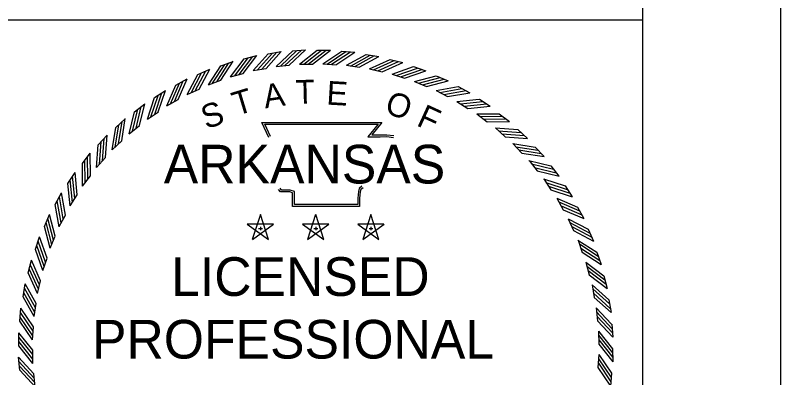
# Model space of a CAD drawing. Extents: x 0 to 1228740, y 0 to 152440.
# Drawn here: x 30.801 to 34, y 18.649 to 20.162 of the extents above; entities that cross this region are included whole.
import ezdxf

# ---------------------------------------------------------------- set-up
doc = ezdxf.new("R2010")
doc.units = 0
doc.layers.add('R_Border', color=7, linetype='Continuous')
doc.layers.add('STAMP_PP', color=7, linetype='Continuous')

msp = doc.modelspace()

# ---------------------------------------------------------------- linework, layer by layer
at = {"layer": 'R_Border'}
for p, q in [((33.4231, 0.5768), (33.4231, 21.4232)), ((29.1131, 20.1432), (33.4231, 20.1432))]:
    msp.add_line(p, q, dxfattribs=at)
msp.add_lwpolyline([(34, 22), (0, 22), (0, 0), (34, 0)], close=True, dxfattribs=at)
at = {"layer": 'STAMP_PP'}
for p, q in [((31.7579, 19.981), (31.8105, 19.9948)), ((31.8584, 20.0015), (31.912, 20.0109)), ((31.9602, 20.0137), (32.0144, 20.0186)), ((32.0633, 20.0167), (32.1177, 20.0167)), ((32.1652, 20.0126), (32.2194, 20.0086)), ((32.2669, 19.9994), (32.3206, 19.9909)), ((31.6595, 19.9522), (31.7108, 19.9703)), ((32.3671, 19.9778), (32.42, 19.965)), ((31.5637, 19.9154), (31.6134, 19.9377)), ((31.7953, 19.9316), (31.849, 19.941)), ((31.8916, 19.9492), (31.9459, 19.9542)), ((31.989, 19.9588), (32.0435, 19.9588)), ((32.0869, 19.9603), (32.1413, 19.9563)), ((32.1845, 19.9538), (32.2384, 19.9453)), ((32.2813, 19.9392), (32.3343, 19.9263)), ((32.4653, 19.9481), (32.5169, 19.9309)), ((31.7008, 19.9061), (31.7536, 19.9199)), ((32.3766, 19.9166), (32.4283, 19.8994)), ((32.5606, 19.9103), (32.6107, 19.8889)), ((31.4714, 19.8708), (31.519, 19.8972)), ((31.6088, 19.8729), (31.6602, 19.891)), ((32.4696, 19.8863), (32.5198, 19.8648)), ((31.383, 19.8188), (31.4283, 19.849)), ((31.5198, 19.8321), (31.5695, 19.8545)), ((32.5598, 19.8484), (32.608, 19.8229)), ((32.6526, 19.8648), (32.7006, 19.8393)), ((31.4344, 19.7842), (31.4821, 19.8106)), ((32.6466, 19.8031), (32.6926, 19.7737)), ((32.7404, 19.8119), (32.7862, 19.7825)), ((31.2992, 19.7596), (31.3419, 19.7934)), ((31.3533, 19.7294), (31.3987, 19.7597)), ((32.7294, 19.7509), (32.7727, 19.7178)), ((32.8235, 19.7518), (32.8668, 19.7188)), ((31.2206, 19.6937), (31.2603, 19.7309)), ((31.277, 19.6681), (31.3198, 19.702)), ((32.8076, 19.692), (32.848, 19.6554)), ((32.9015, 19.6851), (32.9418, 19.6487)), ((31.1477, 19.6216), (31.1842, 19.6619)), ((31.2061, 19.6007), (31.2459, 19.638)), ((32.8806, 19.6268), (32.9179, 19.587)), ((32.9736, 19.6123), (33.0108, 19.5726)), ((31.0811, 19.5437), (31.1141, 19.5869)), ((31.1409, 19.5277), (31.1775, 19.5681)), ((32.948, 19.5558), (32.9819, 19.5131)), ((33.0395, 19.5337), (33.0733, 19.491)), ((31.021, 19.4605), (31.0504, 19.5063)), ((31.082, 19.4495), (31.1151, 19.4928)), ((33.0093, 19.4796), (33.0396, 19.4342)), ((30.9681, 19.3727), (30.9935, 19.4207)), ((33.0987, 19.4499), (33.1288, 19.4046)), ((31.0298, 19.3667), (31.0592, 19.4127)), ((33.0641, 19.3985), (33.0905, 19.3507)), ((33.1507, 19.3615), (33.1771, 19.3139)), ((30.9226, 19.2807), (30.944, 19.3308)), ((30.9845, 19.28), (31.01, 19.3281)), ((31.8255, 19.3302), (31.7915, 19.2258)), ((31.8594, 19.2258), (31.8256, 19.3303)), ((32.0563, 19.3302), (32.0222, 19.2258)), ((32.0902, 19.2258), (32.0564, 19.3303)), ((32.2871, 19.3302), (32.253, 19.2258)), ((32.321, 19.2258), (32.2871, 19.3303)), ((33.112, 19.3131), (33.1344, 19.2634)), ((31.8804, 19.2904), (31.7705, 19.2905)), ((31.7706, 19.2904), (31.8594, 19.2257)), ((31.7916, 19.2258), (31.8805, 19.2903)), ((31.8177, 19.2728), (31.834, 19.2728)), ((31.8256, 19.2787), (31.8256, 19.2649)), ((32.1112, 19.2904), (32.0013, 19.2905)), ((32.0014, 19.2904), (32.0902, 19.2257)), ((32.0224, 19.2258), (32.1113, 19.2903)), ((32.0485, 19.2728), (32.0648, 19.2728)), ((32.0564, 19.2787), (32.0564, 19.2649)), ((32.3419, 19.2904), (32.2321, 19.2905)), ((32.2322, 19.2904), (32.321, 19.2257)), ((32.2532, 19.2258), (32.3421, 19.2903)), ((32.2793, 19.2728), (32.2956, 19.2728)), ((32.2872, 19.2787), (32.2872, 19.2649)), ((33.1953, 19.2692), (33.2176, 19.2195)), ((30.8848, 19.1854), (30.902, 19.237)), ((30.9466, 19.1897), (30.9681, 19.2399)), ((33.1528, 19.2241), (33.1709, 19.1727)), ((33.2321, 19.1734), (33.2502, 19.1221)), ((30.855, 19.0873), (30.8679, 19.1401)), ((30.9163, 19.0967), (30.9335, 19.1484)), ((33.186, 19.1321), (33.1998, 19.0793)), ((33.2608, 19.075), (33.2747, 19.0224)), ((30.8335, 18.987), (30.8419, 19.0407)), ((30.8937, 19.0014), (30.9066, 19.0544)), ((33.2115, 19.0376), (33.2209, 18.9839)), ((33.2814, 18.9745), (33.2908, 18.9209)), ((30.8203, 18.8853), (30.8243, 18.9395)), ((30.8791, 18.9046), (30.8876, 18.9585)), ((33.2291, 18.9413), (33.2341, 18.887)), ((30.8726, 18.807), (30.8766, 18.8614)), ((33.2387, 18.8439), (33.2392, 18.7893)), ((33.2936, 18.8727), (33.2985, 18.8185)), ((30.8155, 18.7828), (30.815, 18.8372)), ((30.8741, 18.7091), (30.8736, 18.7637)), ((33.2973, 18.7702), (33.2978, 18.7158)), ((30.8192, 18.6803), (30.8142, 18.7345)), ((33.2402, 18.746), (33.2362, 18.6916)), ((30.8837, 18.6117), (30.8787, 18.666)), ((33.2925, 18.6677), (33.2885, 18.6135))]:
    msp.add_line(p, q, dxfattribs=at)
for points in [[(31.7535, 19.92), (31.8106, 19.9948)], [(31.7953, 19.9315), (31.8583, 20.0014)], [(31.8126, 19.9344), (31.8756, 20.0043)], [(31.8311, 19.9381), (31.8941, 20.008)], [(31.849, 19.9411), (31.912, 20.011)], [(31.8916, 19.9491), (31.9602, 20.0136)], [(31.909, 19.9506), (31.9776, 20.015)], [(31.9278, 19.9527), (31.9964, 20.0172)], [(31.9458, 19.9542), (32.0145, 20.0187)], [(31.9889, 19.9587), (32.0632, 20.0166)], [(32.0065, 19.9586), (32.0807, 20.0165)], [(32.0254, 19.959), (32.0996, 20.0169)], [(32.0435, 19.9588), (32.1177, 20.0167)], [(32.0868, 19.9603), (32.1651, 20.0126)], [(32.1043, 19.9588), (32.1825, 20.0111)], [(32.1231, 19.9579), (32.2014, 20.0101)], [(32.1412, 19.9564), (32.2195, 20.0087)], [(32.1845, 19.9537), (32.2668, 19.9994)], [(32.2017, 19.9508), (32.2841, 19.9965)], [(31.643, 19.8852), (31.6937, 19.9645)], [(31.6601, 19.8911), (31.7108, 19.9704)], [(31.7008, 19.906), (31.7579, 19.9809)], [(31.7178, 19.9103), (31.7748, 19.9852)], [(31.7359, 19.9155), (31.793, 19.9904)], [(32.2205, 19.9483), (32.3028, 19.994)], [(32.2383, 19.9453), (32.3207, 19.991)], [(32.2812, 19.9391), (32.3671, 19.9778)], [(32.2982, 19.9348), (32.384, 19.9735)], [(32.3167, 19.9308), (32.4025, 19.9695)], [(32.3342, 19.9263), (32.4201, 19.965)], [(31.5694, 19.8545), (31.6134, 19.9378)], [(31.6087, 19.8728), (31.6594, 19.9521)], [(31.6253, 19.8785), (31.676, 19.9578)], [(32.3765, 19.9166), (32.4652, 19.9481)], [(32.393, 19.9109), (32.4818, 19.9424)], [(32.4111, 19.9053), (32.4998, 19.9368)], [(32.4282, 19.8994), (32.517, 19.9309)], [(31.5197, 19.8321), (31.5637, 19.9153)], [(31.5358, 19.8391), (31.5797, 19.9224)], [(31.5528, 19.8472), (31.5968, 19.9305)], [(32.4695, 19.8863), (32.5606, 19.9103)], [(32.4856, 19.8792), (32.5766, 19.9033)], [(31.4344, 19.7842), (31.4713, 19.8707)], [(31.4498, 19.7925), (31.4867, 19.8791)], [(31.4661, 19.802), (31.5031, 19.8886)], [(31.4821, 19.8106), (31.519, 19.8972)], [(32.5031, 19.8722), (32.5941, 19.8962)], [(32.5197, 19.8649), (32.6107, 19.8889)], [(31.3835, 19.7498), (31.4131, 19.8391)], [(31.3986, 19.7597), (31.4283, 19.849)], [(32.5598, 19.8483), (32.6525, 19.8648)], [(32.5752, 19.84), (32.6679, 19.8565)], [(32.5921, 19.8315), (32.6848, 19.848)], [(32.608, 19.8229), (32.7007, 19.8394)], [(31.3533, 19.7293), (31.383, 19.8187)], [(31.368, 19.7389), (31.3976, 19.8283)], [(32.6466, 19.8031), (32.7403, 19.8119)], [(31.3054, 19.6909), (31.3276, 19.7823)], [(31.3197, 19.702), (31.3419, 19.7935)], [(32.6612, 19.7935), (32.755, 19.8023)], [(32.6774, 19.7837), (32.7711, 19.7924)], [(32.6925, 19.7738), (32.7863, 19.7825)], [(31.277, 19.668), (31.2992, 19.7595)], [(31.2908, 19.6788), (31.313, 19.7703)], [(32.7293, 19.7509), (32.8235, 19.7518)], [(32.7431, 19.7401), (32.8373, 19.7411)], [(31.2324, 19.6257), (31.247, 19.7187)], [(31.2458, 19.638), (31.2603, 19.731)], [(31.8606, 19.6525), (31.8316, 19.7154), (32.3333, 19.7156), (32.2914, 19.663), (32.3255, 19.6634), (32.354, 19.6638), (32.3824, 19.6607)], [(31.8678, 19.6559), (31.844, 19.7074), (32.3169, 19.7077), (32.2748, 19.6548), (32.3256, 19.6555), (32.3536, 19.6558), (32.3816, 19.6528)], [(32.7584, 19.729), (32.8526, 19.7299)], [(32.7727, 19.7179), (32.8669, 19.7188)], [(31.2061, 19.6006), (31.2206, 19.6936)], [(31.2189, 19.6125), (31.2335, 19.7055)], [(32.8075, 19.692), (32.9014, 19.6852)], [(32.8204, 19.6801), (32.9143, 19.6733)], [(31.1651, 19.5548), (31.172, 19.6487)], [(31.1774, 19.5681), (31.1842, 19.662)], [(32.8347, 19.6678), (32.9286, 19.6609)], [(32.848, 19.6555), (32.9419, 19.6487)], [(31.1409, 19.5276), (31.1477, 19.6215)], [(31.1528, 19.5405), (31.1596, 19.6344)], [(32.8805, 19.6268), (32.9735, 19.6123)], [(32.8924, 19.6139), (32.9854, 19.5994)], [(31.115, 19.4928), (31.1141, 19.587)], [(32.9056, 19.6004), (32.9986, 19.5859)], [(32.9179, 19.5871), (33.0109, 19.5726)], [(31.0928, 19.4632), (31.0918, 19.5574)], [(31.1039, 19.4785), (31.1029, 19.5727)], [(32.9479, 19.5559), (33.0394, 19.5337)], [(31.082, 19.4494), (31.0811, 19.5436)], [(32.9587, 19.542), (33.0502, 19.5199)], [(32.9708, 19.5275), (33.0622, 19.5053)], [(31.0492, 19.3975), (31.0405, 19.4912)], [(31.0591, 19.4126), (31.0504, 19.5064)], [(32.9819, 19.5132), (33.0734, 19.491)], [(31.0298, 19.3667), (31.021, 19.4604)], [(31.0393, 19.3813), (31.0306, 19.4751)], [(33.0092, 19.4796), (33.0986, 19.4499)], [(33.0188, 19.4649), (33.1082, 19.4353)], [(31.01, 19.3281), (30.9935, 19.4208)], [(32.2543, 19.4423), (32.2457, 19.4353), (32.2429, 19.4249), (32.24, 19.3989), (32.24, 19.3642), (31.9599, 19.3642), (31.9599, 19.411), (31.9599, 19.4214), (31.9486, 19.4249), (31.9087, 19.4249), (31.9016, 19.4357)], [(32.2493, 19.4484), (32.2387, 19.4399), (32.235, 19.4264), (32.2321, 19.3993), (32.2321, 19.3721), (31.9679, 19.3721), (31.9679, 19.411), (31.9679, 19.4273), (31.9497, 19.4328), (31.913, 19.4328), (31.9083, 19.4401)], [(33.0296, 19.4494), (33.119, 19.4198)], [(33.0396, 19.4343), (33.1289, 19.4046)], [(30.9929, 19.2953), (30.9764, 19.388)], [(31.0013, 19.3122), (30.9849, 19.4049)], [(33.064, 19.3985), (33.1506, 19.3616)], [(30.9845, 19.2799), (30.9681, 19.3726)], [(33.0724, 19.3831), (33.159, 19.3462)], [(33.0819, 19.3668), (33.1685, 19.3298)], [(30.968, 19.2398), (30.944, 19.3308)], [(33.0905, 19.3508), (33.1771, 19.3139)], [(30.9537, 19.2057), (30.9296, 19.2967)], [(30.9607, 19.2232), (30.9367, 19.3142)], [(33.112, 19.3132), (33.1952, 19.2692)], [(33.119, 19.2971), (33.2023, 19.2532)], [(30.9466, 19.1896), (30.9226, 19.2807)], [(33.1271, 19.2801), (33.2104, 19.2361)], [(33.1344, 19.2635), (33.2177, 19.2195)], [(30.9335, 19.1484), (30.902, 19.2371)], [(30.922, 19.1131), (30.8905, 19.2019)], [(30.9276, 19.1312), (30.8961, 19.2199)], [(33.1527, 19.2242), (33.232, 19.1735)], [(33.1584, 19.2076), (33.2377, 19.1569)], [(30.9163, 19.0966), (30.8848, 19.1853)], [(33.1651, 19.1899), (33.2444, 19.1392)], [(33.1709, 19.1728), (33.2503, 19.1221)], [(30.9066, 19.0544), (30.8679, 19.1402)], [(33.1859, 19.1321), (33.2608, 19.075)], [(30.8981, 19.0183), (30.8594, 19.1041)], [(30.9021, 19.0368), (30.8634, 19.1226)], [(33.1902, 19.1151), (33.2651, 19.0581)], [(30.8938, 19.0013), (30.8551, 19.0872)], [(33.1954, 19.097), (33.2703, 19.0399)], [(33.1999, 19.0794), (33.2747, 19.0223)], [(30.8876, 18.9585), (30.8419, 19.0408)], [(33.2114, 19.0376), (33.2813, 18.9746)], [(30.8821, 18.9218), (30.8364, 19.0042)], [(30.8846, 18.9406), (30.8389, 19.0229)], [(33.2143, 19.0203), (33.2842, 18.9573)], [(30.8792, 18.9046), (30.8335, 18.9869)], [(33.218, 19.0018), (33.2879, 18.9387)], [(33.221, 18.9839), (33.2909, 18.9209)], [(30.8765, 18.8613), (30.8242, 18.9396)], [(33.229, 18.9413), (33.2935, 18.8727)], [(30.875, 18.8432), (30.8227, 18.9215)], [(33.2305, 18.9239), (33.2949, 18.8553)], [(30.8726, 18.8069), (30.8203, 18.8852)], [(30.8741, 18.8244), (30.8218, 18.9026)], [(33.2326, 18.9051), (33.2971, 18.8365)], [(33.2341, 18.887), (33.2986, 18.8184)], [(33.2386, 18.8439), (33.2972, 18.7702)], [(30.8736, 18.7636), (30.815, 18.8373)], [(30.8736, 18.7455), (30.815, 18.8192)], [(33.2386, 18.8264), (33.2972, 18.7527)], [(30.8741, 18.7266), (30.8156, 18.8003)], [(30.8741, 18.7091), (30.8156, 18.7828)], [(33.2392, 18.8075), (33.2978, 18.7338)], [(33.2392, 18.7894), (33.2978, 18.7157)], [(30.8787, 18.666), (30.8142, 18.7346)], [(30.8802, 18.6479), (30.8157, 18.7165)], [(33.2387, 18.7286), (33.291, 18.6503)], [(33.2402, 18.7461), (33.2925, 18.6678)], [(30.8823, 18.6291), (30.8178, 18.6977)], [(33.2363, 18.6917), (33.2885, 18.6134)], [(33.2378, 18.7098), (33.29, 18.6315)], [(30.8838, 18.6117), (30.8193, 18.6803)]]:
    msp.add_lwpolyline(points, dxfattribs=at)

# ---------------------------------------------------------------- texts
for s, rotation, p in [('A', 8.6788, (31.8453, 19.7733)), ('T', 1.4789, (31.9731, 19.793)), ('E', 356.672, (32.0998, 19.79)), ('T', 16.9015, (31.7251, 19.742)), ('O', 341.2218, (32.3401, 19.7561)), ('S', 19.7726, (31.5992, 19.6855)), ('F', 335.3628, (32.4735, 19.7039))]:
    msp.add_text(s, height=0.099, rotation=rotation, dxfattribs=at).set_placement(p)
for s, height, p in [('ARKANSAS', 0.16155, (31.4214, 19.4603)), ('LICENSED', 0.16155, (31.4521, 18.9908)), ('PROFESSIONAL', 0.161547, (31.1214, 18.7292))]:
    msp.add_text(s, height=height, dxfattribs=at).set_placement(p)

doc.saveas('drawing.dxf')
